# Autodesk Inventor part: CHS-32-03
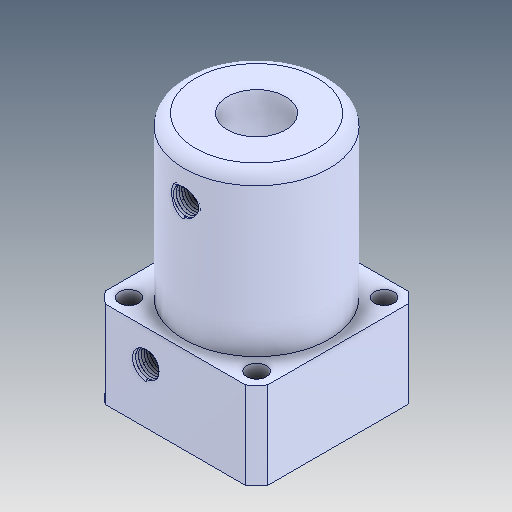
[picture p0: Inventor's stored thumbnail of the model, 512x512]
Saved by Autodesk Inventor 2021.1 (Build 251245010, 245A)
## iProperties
Created: 2021-05
Part Number: CHS-32-03
Material: Ogólny
Document SubType Name: Modeling
Designer: user
Density: 1 g/cm^3
Appearance: Domyślna
Author: user
Revision Number: ÈÎºÎ
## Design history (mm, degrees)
feature "Í¹Ì¨-À­Éì1"
node "Bryła1"
